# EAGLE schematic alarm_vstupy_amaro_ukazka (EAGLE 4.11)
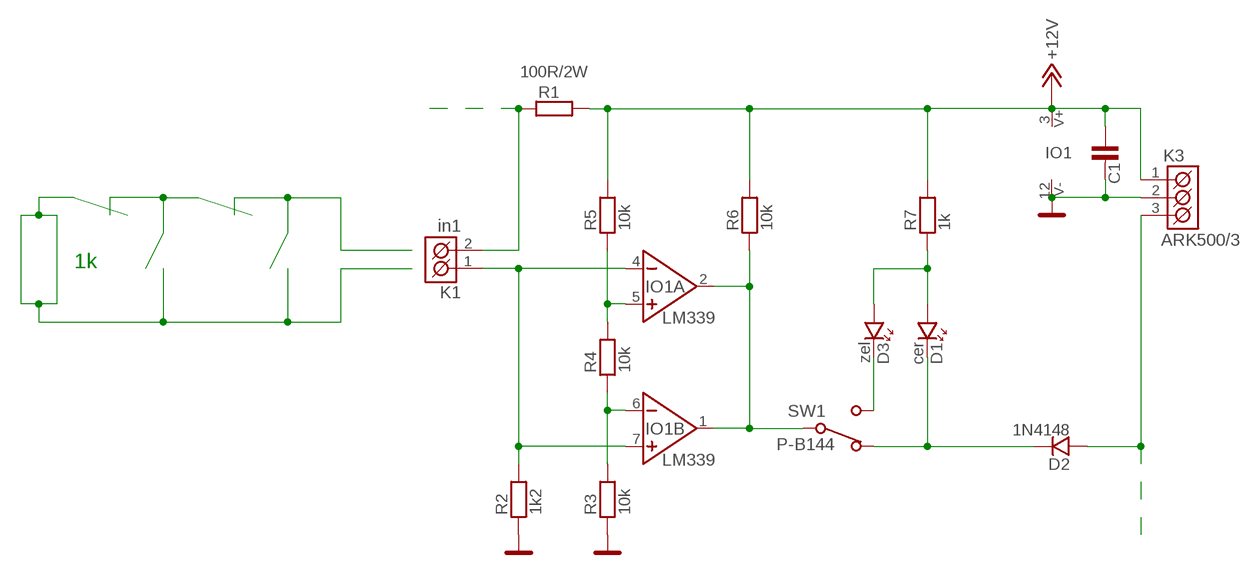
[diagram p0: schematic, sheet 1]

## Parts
C1  C-KERAMIK_SMD_1206  [1206]
D1  cer  LED_3  [LED_3]
D2  1N4148  1N4148_7,5  [D-7,5]
D3  zel  LED_3  [LED_3]
IO1  LM339  [DIL14]
K1  in1  ARK500/2  [ARK500/2]
K3  ARK500/3  [ARK500/3]
R1  100R/2W  R__2W  [R-_2W]
R2  1k2  R_7,5  [R-7,5]
R3  10k  R_7,5  [R-7,5]
R4  10k  R_7,5  [R-7,5]
R5  10k  R_7,5  [R-7,5]
R6  10k  R_7,5  [R-7,5]
R7  1k  R_7,5  [R-7,5]
SW1  P-B144  [P-B144]

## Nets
+12V: C1.1 IO1.3(N:V+) K3.1(K1) R1.2 R5.2 R6.2 R7.2
GND: C1.2 IO1.12(N:V-) K3.2(K2) R2.1 R3.1
N$1: IO1.6(B:IN-) R3.2 R4.1
N$2: IO1.5(A:NEIN+) R4.2 R5.1
N$3: IO1.4(A:IN-) IO1.7(B:NEIN+) K1.1(K1) R2.2
N$5: IO1.1(B:VYSTUP) IO1.2(A:VYSTUP) R6.1 SW1.2
N$6: D1.A D3.A R7.1
N$7: D2.A K3.3(K3)
N$8: D3.K SW1.1
N$9: D1.K D2.K SW1.3
N$13: K1.2(K2) R1.1
Unconnected: IO1.8(C:IN-) IO1.9(C:NEIN+) IO1.10(D:IN-) IO1.11(D:NEIN+) IO1.13(D:VYSTUP) IO1.14(C:VYSTUP)

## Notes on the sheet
- 1k

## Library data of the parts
C1 = #PaJa_15:C-KERAMIK: Kondenzator - keramicky
D1 D3 = #PaJa_15:LED: LED - jednobarevna
D2 = #PaJa_15:1N4148: Univerzalni dioda - 0,15A, 75V
IO1 = #PaJa_15:LM339: Komparator - 4x - nizkoprikonovy
K1 = #PaJa_13:ARK500/2: Svorkovnice - roztec 5mm - dvojita
K3 = #PaJa_14:ARK500/3: Svorkovnice - roztec 5mm - trojita
R1-R7 = #PaJa_15:R: Rezistor
SW1 = #PaJa_15:P-B144: Posuvny prepinac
